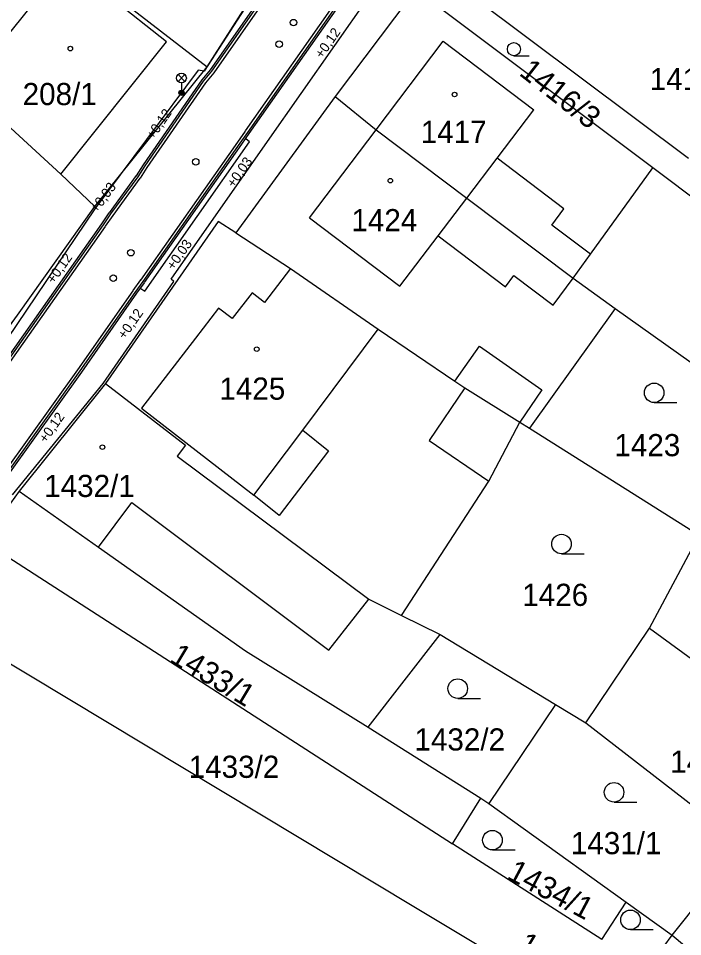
# Model space of a CAD drawing. Extents: x -600849 to -599899, y -1204328 to -1203436.
# Drawn here: x -600363.4 to -600312.4, y -1203786 to -1203715.5 of the extents above; entities that cross this region are included whole.
import ezdxf

# ---------------------------------------------------------------- set-up
doc = ezdxf.new("R2010")
doc.units = 0
for name, color, linetype in [('Vrstva 1', 7, 'Continuous'), ('Vrstva 10', 7, 'Continuous'), ('Vrstva 11', 7, 'Continuous'), ('Vrstva 2', 7, 'Continuous'), ('Vrstva 28', 7, 'Continuous'), ('Vrstva 3', 7, 'Continuous'), ('Vrstva 33', 7, 'Continuous'), ('Vrstva 4', 7, 'Continuous'), ('Vrstva 42', 7, 'Continuous'), ('Vrstva 5', 7, 'Continuous')]:
    doc.layers.add(name, color=color, linetype=linetype)

msp = doc.modelspace()

# ---------------------------------------------------------------- linework, layer by layer
at = {"layer": 'Vrstva 1'}
for p, q in [((-600348.91, -1203719.22), (-600340.89, -1203706.64)), ((-600331.6, -1203711.54), (-600311.99, -1203726.24)), ((-600332.92, -1203713.3), (-600339.11, -1203721.5)), ((-600314.72, -1203726.98), (-600332.92, -1203713.3)), ((-600357.54, -1203729.93), (-600348.91, -1203719.22)), ((-600339.11, -1203721.5), (-600346.73, -1203731.96)), ((-600308.05, -1203732), (-600314.72, -1203726.98)), ((-600320.85, -1203735.43), (-600317.61, -1203737.76)), ((-600317.61, -1203737.76), (-600324.2, -1203746.96)), ((-600317.61, -1203737.76), (-600305.94, -1203746.1)), ((-600356.72, -1203743.53), (-600363.34, -1203751.79)), ((-600324.93, -1203746.5), (-600324.2, -1203746.96)), ((-600324.2, -1203746.96), (-600311.16, -1203755.18)), ((-600363.34, -1203751.79), (-600366.13, -1203755.61)), ((-600366.13, -1203755.61), (-600330.09, -1203778.87)), ((-600314.97, -1203762.31), (-600311.16, -1203755.18)), ((-600334, -1203761.34), (-600331.04, -1203762.8)), ((-600336.57, -1203769.92), (-600331.04, -1203762.8)), ((-600331.04, -1203762.8), (-600322.2, -1203768.17)), ((-600319.87, -1203769.58), (-600314.97, -1203762.31)), ((-600314.97, -1203762.31), (-600302.12, -1203771.73)), ((-600322.2, -1203768.17), (-600327.3, -1203775.78)), ((-600322.2, -1203768.17), (-600319.87, -1203769.58)), ((-600319.87, -1203769.58), (-600307.78, -1203778.94)), ((-600336.57, -1203769.92), (-600327.91, -1203775.35)), ((-600330.09, -1203778.87), (-600327.91, -1203775.35)), ((-600327.91, -1203775.35), (-600327.3, -1203775.78)), ((-600327.3, -1203775.78), (-600316.77, -1203783.34)), ((-600318.64, -1203786.2), (-600330.09, -1203778.87)), ((-600313.23, -1203785.88), (-600307.78, -1203778.94)), ((-600318.64, -1203786.2), (-600316.77, -1203783.34)), ((-600316.77, -1203783.34), (-600313.23, -1203785.88)), ((-600315.21, -1203788.5), (-600313.23, -1203785.88))]:
    msp.add_line(p, q, dxfattribs=at)
for points in [[(-600365.63, -1203706.06), (-600363, -1203707.66), (-600361.09, -1203708.81), (-600361.02, -1203709.84), (-600356.07, -1203713.68), (-600348.91, -1203719.22)], [(-600372.42, -1203717.46), (-600367.63, -1203721.01), (-600365.29, -1203722.74), (-600360.15, -1203727.46), (-600357.54, -1203729.93)], [(-600339.11, -1203721.5), (-600335.95, -1203724.05), (-600329, -1203729.29), (-600320.85, -1203735.43)], [(-600320.85, -1203735.43), (-600319.52, -1203733.61), (-600314.72, -1203726.98)], [(-600364.42, -1203739.59), (-600363.48, -1203738.27), (-600357.54, -1203729.93)], [(-600346.73, -1203731.96), (-600348.07, -1203731.08), (-600356.72, -1203743.53)], [(-600346.73, -1203731.96), (-600342.52, -1203734.71), (-600335.79, -1203739.36), (-600329.91, -1203743.36), (-600329.14, -1203743.85), (-600324.93, -1203746.5)], [(-600356.72, -1203743.53), (-600350.59, -1203748.27), (-600351.22, -1203749.1), (-600336.52, -1203760.09), (-600334, -1203761.34)], [(-600334, -1203761.34), (-600327.32, -1203751.03), (-600324.93, -1203746.5)], [(-600363.34, -1203751.79), (-600357.27, -1203756.08), (-600345.98, -1203764.05), (-600336.57, -1203769.92)], [(-600365.51, -1203764.14), (-600333.06, -1203783.67), (-600318.28, -1203792.54)], [(-600313.23, -1203785.88), (-600304.57, -1203793.13), (-600303.04, -1203791.27), (-600297.42, -1203795.98), (-600298.94, -1203797.84), (-600296.63, -1203799.77)]]:
    msp.add_lwpolyline(points, dxfattribs=at)
at = {"layer": 'Vrstva 10'}
for p, q in [((-600339.46, -1203706.52), (-600348.58, -1203719.55)), ((-600345.81, -1203724.26), (-600338.34, -1203713.6)), ((-600348.58, -1203719.55), (-600349.22, -1203720.32)), ((-600349.22, -1203720.32), (-600353.71, -1203726.83)), ((-600346.38, -1203725.08), (-600345.81, -1203724.26)), ((-600353.84, -1203735.7), (-600346.38, -1203725.08)), ((-600353.71, -1203726.83), (-600354.24, -1203727.66)), ((-600354.24, -1203727.66), (-600356.33, -1203730.51)), ((-600356.33, -1203730.51), (-600356.9, -1203731.35)), ((-600356.9, -1203731.35), (-600368.24, -1203747.46)), ((-600354.45, -1203736.54), (-600353.84, -1203735.7)), ((-600358.67, -1203742.56), (-600354.45, -1203736.54)), ((-600364.27, -1203750.41), (-600358.67, -1203742.56))]:
    msp.add_line(p, q, dxfattribs=at)
at = {"layer": 'Vrstva 11'}
for p, q in [((-600339.583, -1203706.434), (-600348.701, -1203719.462)), ((-600340.82, -1203706.68), (-600349.16, -1203719.55)), ((-600339.296, -1203706.635), (-600348.42, -1203719.672)), ((-600345.974, -1203724.145), (-600338.491, -1203713.467)), ((-600345.687, -1203724.346), (-600338.217, -1203713.686)), ((-600344.29, -1203724.94), (-600336.42, -1203713.7)), ((-600349.6, -1203719.47), (-600357.53, -1203730.13)), ((-600349.16, -1203719.55), (-600349.6, -1203719.47)), ((-600348.701, -1203719.462), (-600349.337, -1203720.227)), ((-600348.42, -1203719.672), (-600349.058, -1203720.439)), ((-600349.337, -1203720.227), (-600353.833, -1203726.745)), ((-600349.058, -1203720.439), (-600353.545, -1203726.944)), ((-600346.572, -1203725.007), (-600345.974, -1203724.146)), ((-600346.257, -1203725.166), (-600345.687, -1203724.346)), ((-600345.68, -1203724.98), (-600345.96, -1203724.76)), ((-600354.003, -1203735.585), (-600346.572, -1203725.007)), ((-600353.717, -1203735.786), (-600346.257, -1203725.166)), ((-600353.7, -1203736.43), (-600345.68, -1203724.98)), ((-600351.67, -1203735.52), (-600344.29, -1203724.94)), ((-600353.836, -1203726.749), (-600354.366, -1203727.579)), ((-600354.361, -1203727.571), (-600356.451, -1203730.421)), ((-600353.541, -1203726.937), (-600354.071, -1203727.767)), ((-600354.079, -1203727.778), (-600356.169, -1203730.628)), ((-600357.53, -1203730.13), (-600368.98, -1203747.04)), ((-600356.454, -1203730.426), (-600357.024, -1203731.266)), ((-600356.164, -1203730.623), (-600356.734, -1203731.463)), ((-600357.023, -1203731.264), (-600368.395, -1203747.419)), ((-600356.737, -1203731.465), (-600368.156, -1203747.687)), ((-600356.9, -1203743.52), (-600351.48, -1203735.69)), ((-600354.595, -1203736.398), (-600354.002, -1203735.582)), ((-600354.312, -1203736.604), (-600353.719, -1203735.788)), ((-600351.48, -1203735.69), (-600351.67, -1203735.52)), ((-600358.85, -1203742.468), (-600354.599, -1203736.403)), ((-600358.547, -1203742.646), (-600354.312, -1203736.604)), ((-600354.02, -1203736.23), (-600353.7, -1203736.43)), ((-600364.434, -1203750.296), (-600358.85, -1203742.468)), ((-600364.14, -1203750.486), (-600358.548, -1203742.647)), ((-600363.85, -1203752.08), (-600356.9, -1203743.52))]:
    msp.add_line(p, q, dxfattribs=at)
at = {"layer": 'Vrstva 28'}
for centre in [(-600342.29, -1203715.83), (-600343.39, -1203717.48), (-600349.8, -1203726.51), (-600354.77, -1203733.49), (-600356.12, -1203735.44)]:
    msp.add_circle(centre, 0.25, dxfattribs=at)
at = {"layer": 'Vrstva 3'}
for p, q in [((-600325.385, -1203718.37), (-600324.213, -1203718.37)), ((-600314.623, -1203744.99), (-600312.873, -1203744.99)), ((-600321.733, -1203756.6), (-600319.983, -1203756.6)), ((-600329.693, -1203767.7), (-600327.943, -1203767.7)), ((-600317.703, -1203775.66), (-600315.953, -1203775.66)), ((-600327.033, -1203779.33), (-600325.283, -1203779.33)), ((-600316.443, -1203785.45), (-600314.693, -1203785.45))]:
    msp.add_line(p, q, dxfattribs=at)
for centre, radius in [((-600325.385, -1203717.867), 0.502), ((-600314.623, -1203744.24), 0.75), ((-600321.733, -1203755.85), 0.75), ((-600329.693, -1203766.95), 0.75), ((-600317.703, -1203774.91), 0.75), ((-600327.033, -1203778.58), 0.75), ((-600316.443, -1203784.7), 0.75)]:
    msp.add_circle(centre, radius, dxfattribs=at)
at = {"layer": 'Vrstva 33'}
for p, q in [((-600351.155, -1203720.35), (-600350.625, -1203719.82)), ((-600351.155, -1203719.82), (-600350.625, -1203720.35)), ((-600350.89, -1203720.46), (-600350.89, -1203721.21))]:
    msp.add_line(p, q, dxfattribs=at)
for centre, radius in [((-600350.89, -1203720.085), 0.375), ((-600350.89, -1203721.21), 0.2), ((-600350.89, -1203721.21), 0.145), ((-600350.89, -1203721.21), 0.0876)]:
    msp.add_circle(centre, radius, dxfattribs=at)
at = {"layer": 'Vrstva 4'}
for p, q in [((-600359.72, -1203711.15), (-600367.63, -1203721.01)), ((-600352.03, -1203717.3), (-600359.72, -1203711.15)), ((-600360.15, -1203727.46), (-600352.03, -1203717.3)), ((-600335.95, -1203724.05), (-600330.81, -1203717.26)), ((-600330.81, -1203717.26), (-600323.86, -1203722.52)), ((-600326.68, -1203726.24), (-600323.86, -1203722.52)), ((-600341.07, -1203730.82), (-600335.95, -1203724.05)), ((-600329, -1203729.29), (-600326.68, -1203726.24)), ((-600321.56, -1203730.12), (-600326.68, -1203726.24)), ((-600331.2, -1203732.2), (-600329, -1203729.29)), ((-600322.47, -1203731.37), (-600321.56, -1203730.12)), ((-600341.07, -1203730.82), (-600334.13, -1203736.06)), ((-600319.52, -1203733.61), (-600322.47, -1203731.37)), ((-600334.13, -1203736.06), (-600331.2, -1203732.2)), ((-600331.2, -1203732.2), (-600326.04, -1203736.11)), ((-600342.52, -1203734.71), (-600344.51, -1203737.32)), ((-600326.04, -1203736.11), (-600325.38, -1203735.23)), ((-600325.38, -1203735.23), (-600322.38, -1203737.51)), ((-600322.38, -1203737.51), (-600320.85, -1203735.43)), ((-600345.48, -1203736.58), (-600346.99, -1203738.54)), ((-600344.51, -1203737.32), (-600345.48, -1203736.58)), ((-600348.05, -1203737.75), (-600349.81, -1203740.04)), ((-600346.99, -1203738.54), (-600348.05, -1203737.75)), ((-600341.58, -1203747.12), (-600335.79, -1203739.36)), ((-600349.81, -1203740.04), (-600353.96, -1203745.43)), ((-600329.91, -1203743.36), (-600328.02, -1203740.67)), ((-600328.02, -1203740.67), (-600323.25, -1203744.01)), ((-600329.14, -1203743.85), (-600331.88, -1203747.91)), ((-600323.25, -1203744.01), (-600324.93, -1203746.5)), ((-600353.96, -1203745.43), (-600345.34, -1203752.11)), ((-600345.34, -1203752.11), (-600341.58, -1203747.12)), ((-600341.58, -1203747.12), (-600339.6, -1203748.7)), ((-600331.88, -1203747.91), (-600327.32, -1203751.03)), ((-600339.6, -1203748.7), (-600343.39, -1203753.65)), ((-600343.39, -1203753.65), (-600345.34, -1203752.11)), ((-600357.27, -1203756.08), (-600354.7, -1203752.65)), ((-600354.7, -1203752.65), (-600339.59, -1203763.99)), ((-600339.59, -1203763.99), (-600336.52, -1203760.09))]:
    msp.add_line(p, q, dxfattribs=at)
at = {"layer": 'Vrstva 5'}
for centre in [(-600359.417, -1203717.819), (-600329.937, -1203721.349), (-600334.867, -1203727.959), (-600345.117, -1203740.889), (-600356.957, -1203748.419)]:
    msp.add_circle(centre, 0.175, dxfattribs=at)

# ---------------------------------------------------------------- texts
at = {"layer": 'Vrstva 2'}
for s, rotation, p in [('1416/3', 322, (-600325.064, -1203719.799)), ('1433/1', 329, (-600351.891, -1203764.825)), ('1434/1', 332, (-600326.014, -1203781.487)), ('1434/2', 329, (-600325.231, -1203786.985))]:
    msp.add_text(s, height=1.7, rotation=rotation, dxfattribs=at).set_placement(p)
for s, p in [('1416/1', (-600314.967, -1203721.01)), ('208/1', (-600363.078, -1203722.16)), ('1417', (-600332.534, -1203725.06)), ('1424', (-600337.854, -1203731.84)), ('1425', (-600347.984, -1203744.77)), ('1423', (-600317.674, -1203749.11)), ('1432/1', (-600361.427, -1203752.24)), ('1426', (-600324.744, -1203760.6)), ('1432/2', (-600333.017, -1203771.7)), ('1430', (-600313.394, -1203773.4)), ('1433/2', (-600350.337, -1203773.8)), ('1431/1', (-600321.017, -1203779.66))]:
    msp.add_text(s, height=1.7, dxfattribs=at).set_placement(p)
at = {"layer": 'Vrstva 42'}
for s, rotation, p in [('+0,12', 54.97913, (-600340.101, -1203718.639)), ('+0,12', 55.40566, (-600353.045, -1203724.861)), ('+0,03', 54.91394, (-600346.866, -1203728.555)), ('+0,03', 53.74616, (-600357.366, -1203730.485)), ('+0,03', 54.91394, (-600351.493, -1203734.881)), ('+0,12', 54.85711, (-600360.686, -1203735.93)), ('+0,12', 54.96967, (-600355.24, -1203740.193)), ('+0,12', 54.49686, (-600361.293, -1203748.149))]:
    msp.add_text(s, height=0.75, rotation=rotation, dxfattribs=at).set_placement(p)

doc.saveas('drawing.dxf')
